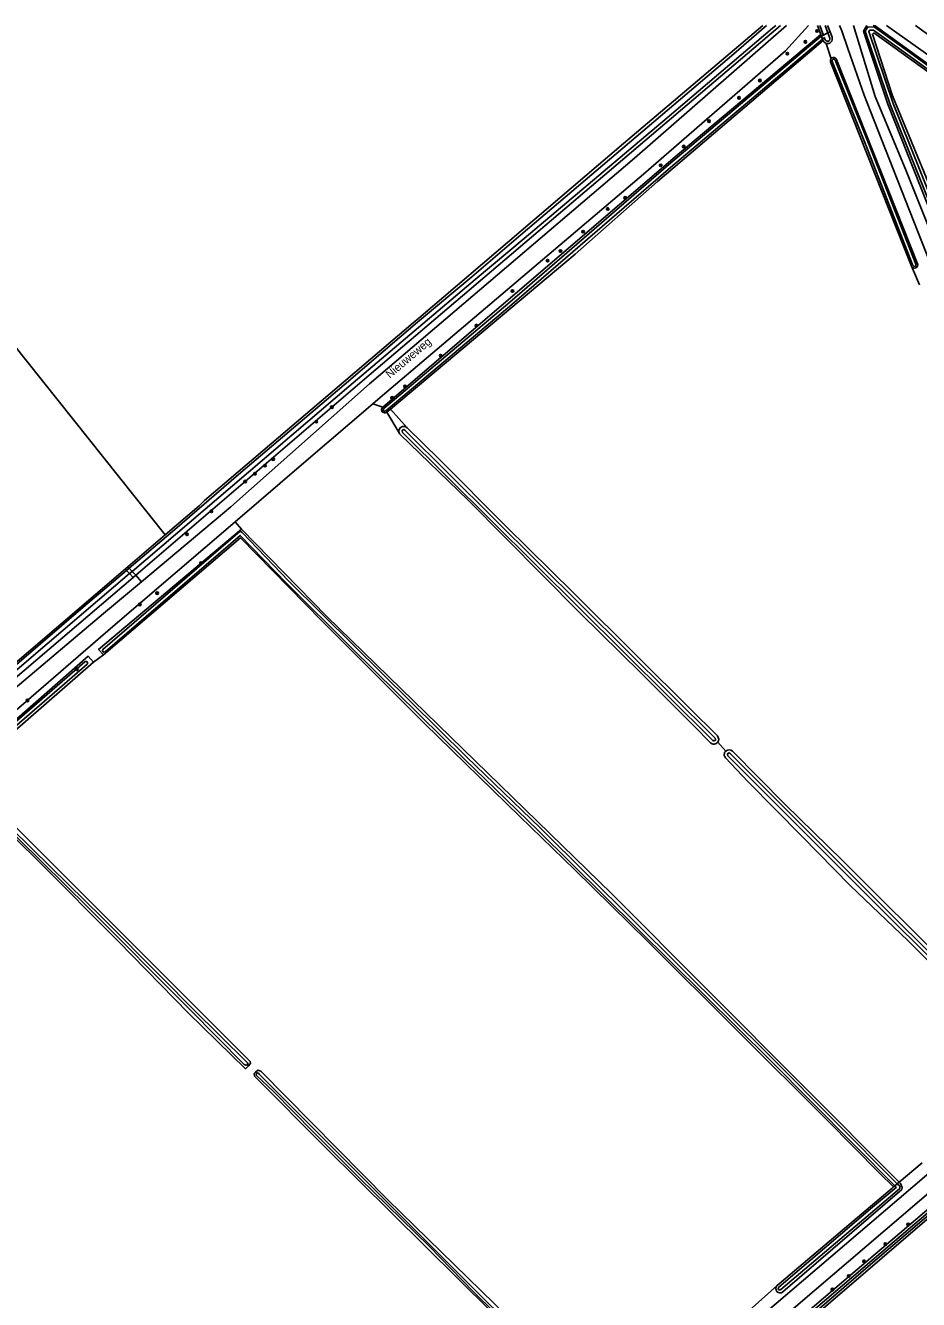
# Model space of a CAD drawing. Extents: x 141000 to 143000, y 400580 to 403500.
# Drawn here: x 142326.5 to 142605.5, y 403101.9 to 403500 of the extents above; entities that cross this region are included whole.
import ezdxf

# ---------------------------------------------------------------- set-up
doc = ezdxf.new("R2010")
doc.units = 0
for name, color, linetype in [('gg-anno-openbare ruimte label', 7, 'Continuous'), ('gg-knt-bronhoudergrens', 7, 'Continuous'), ('gg-knt-onverhard', 7, 'Continuous'), ('gg-knt-verharding', 7, 'Continuous'), ('gg-kntw-bovenkant insteek waterloop', 7, 'Continuous'), ('gg-kntw-waterlijn', 7, 'Continuous'), ('gg-kwrk-kunstwerk niveau 01', 7, 'Continuous'), ('gt-grn-groengrens', 7, 'Continuous'), ('gt-grn-vlakafsluiter', 7, 'Continuous'), ('gt-symb-boom', 7, 'Continuous')]:
    doc.layers.add(name, color=color, linetype=linetype)

# ---------------------------------------------------------------- blocks, each defined once
blk = doc.blocks.new('gt0-BOOM')
at = {"layer": 'gt-symb-boom'}
for radius in [0.4, 0.2]:
    blk.add_circle((0, 0), radius, dxfattribs=at)

msp = doc.modelspace()

# ---------------------------------------------------------------- linework, layer by layer
at = {"layer": 'gg-knt-bronhoudergrens'}
for p, q in [((142578.16, 403489.54), (142576.6, 403494.39)), ((142434.98, 403381.73), (142438.11, 403380.73)), ((142392, 403344.92), (142393.95, 403342.64)), ((142347.75, 403301), (142350.85, 403303.33)), ((142606.6, 403144.58), (142599.46, 403138.52)), ((142561.35, 403106.23), (142552.56, 403098.43))]:
    msp.add_line(p, q, dxfattribs=at)
at = {"layer": 'gg-knt-onverhard'}
for p, q in [((142370.19, 403340.85), (142264.78, 403472.87)), ((142603.33, 403424.78), (142605.82, 403418.96)), ((142439.4, 403379.2), (142443.25, 403372.7)), ((142440.52, 403380.15), (142445.72, 403374.27)), ((142545.29, 403273.28), (142542.79, 403276.02))]:
    msp.add_line(p, q, dxfattribs=at)
msp.add_lwpolyline([(142392, 403344.92), (142413.49, 403363.32), (142434.98, 403381.73)], dxfattribs=at)
at = {"layer": 'gg-knt-verharding'}
for points in [[(142362.71, 403326.12), (142390.63, 403349.55), (142434.03, 403388), (142516.8, 403458.52), (142564.26, 403500)], [(142434.98, 403381.73), (142437.3, 403383.72), (142519.54, 403453.56), (142563.96, 403492.12), (142571.1, 403500)], [(142580.86, 403500), (142581.54, 403498.3), (142583.38, 403492.84), (142588.51, 403478.21), (142592.66, 403467.56), (142616.56, 403406.94), (142630.76, 403372.28), (142649.91, 403327.04), (142662.96, 403294.46), (142683.41, 403242.72), (142693.01, 403213.78)], [(142585.17, 403500), (142591.93, 403477.83), (142601.39, 403455.15), (142647.31, 403340.12), (142678.4, 403262.94), (142686.61, 403242.88), (142692.87, 403227.3), (142697.08, 403214.59)], [(142595.45, 403500), (142629.17, 403476.1), (142673.83, 403443.54), (142712.26, 403416.36), (142765.07, 403379.18), (142812.16, 403344.83), (142845.71, 403319.06)], [(142604.52, 403500), (142632.22, 403479.92), (142678.54, 403445.48), (142714.62, 403419.55), (142767.02, 403382.42), (142814.6, 403347.5), (142848.6, 403321.46)], [(142129.43, 403121.45), (142155.13, 403142.95), (142217.83, 403196.26), (142255.83, 403229.33), (142298.44, 403265.98), (142313.46, 403277.45), (142353.81, 403312.2), (142392, 403344.92)], [(142362.71, 403326.12), (142350.92, 403316.23), (142295.63, 403269.59), (142253.14, 403232.93), (142215.27, 403199.68), (142179.13, 403169.58), (142151.11, 403147.23), (142116.02, 403117.12)], [(142479.87, 403025.12), (142638.66, 403160.83), (142676.84, 403193.65), (142683.65, 403199.18)], [(142674.81, 403197.87), (142603.73, 403137.12), (142467.85, 403021.07), (142458.4, 403012.83)]]:
    msp.add_lwpolyline(points, dxfattribs=at)
at = {"layer": 'gg-kntw-bovenkant insteek waterloop'}
for p, q in [((142573.89, 403500), (142574.94, 403497.22)), ((142577.1, 403500), (142577.86, 403497.99)), ((142577.86, 403497.99), (142578.48, 403496.34)), ((142579.91, 403489.34), (142605.17, 403425.56)), ((142578.05, 403488.6), (142603.33, 403424.78)), ((142440.52, 403380.15), (142439.4, 403379.2)), ((142358.48, 403330.82), (142370.19, 403340.85)), ((142308.84, 403267.11), (142347.75, 403301))]:
    msp.add_line(p, q, dxfattribs=at)
for points in [[(142360.96, 403328.21), (142433.9, 403390.74), (142562.39, 403500)], [(142370.19, 403340.85), (142380.73, 403349.88), (142382.43, 403351.52), (142447.61, 403407.09), (142449.39, 403408.56), (142513.33, 403463.13), (142556.85, 403500)], [(142574.94, 403497.22), (142573.01, 403495.54), (142530.23, 403459.57), (142438.11, 403380.73)], [(142589.32, 403500), (142588.32, 403498.23), (142595.87, 403475.4), (142640.71, 403362.28), (142654.81, 403325.96), (142665.77, 403298.81)], [(142706.45, 403413.83), (142670.95, 403440.11), (142621.19, 403476.34), (142591.57, 403497.67), (142591.07, 403497.32), (142597.37, 403478.02), (142617.11, 403430.15), (142651.96, 403339.43), (142667.73, 403300.2)], [(142591.29, 403500), (142591.97, 403499.88), (142622.44, 403477.83), (142672.13, 403441.68), (142707.63, 403415.45)], [(142440.52, 403380.15), (142498.24, 403428.49), (142523.95, 403451.27), (142575.67, 403495.29)], [(142445.72, 403374.27), (142455.72, 403364.51), (142476.68, 403343.4), (142497.61, 403322.83), (142518.26, 403302.28), (142533.82, 403286.76), (142542.65, 403277.99)], [(142540.53, 403275.86), (142535.49, 403280.89), (142518.85, 403297.65), (142499.67, 403316.48), (142464.83, 403351.63), (142443.54, 403372.2)], [(142350.85, 403303.33), (142349.35, 403305.04), (142393.95, 403342.64)], [(142393.95, 403342.64), (142420.59, 403315.46), (142509.69, 403228.66), (142599.46, 403138.52)], [(142350.85, 403303.33), (142393.65, 403339.89), (142418.94, 403314.04), (142451.22, 403281.81), (142480.92, 403252.78), (142498.12, 403236.12), (142520.84, 403213.86), (142577.06, 403157.85), (142593.32, 403141.35), (142597.66, 403137.08)], [(142299.37, 403280.46), (142327.45, 403304.24), (142358.48, 403330.82)], [(142360.17, 403327.53), (142350.24, 403319.02), (142301.84, 403277.83)], [(142347.75, 403301), (142346.08, 403302.9), (142307.25, 403268.89)], [(142640.83, 403175.69), (142632.08, 403184.36), (142617.37, 403198.78), (142602.25, 403214), (142584.13, 403231.28), (142569.16, 403246.61), (142552.14, 403263.78), (142545.24, 403271.12)], [(142547.36, 403273.24), (142563.78, 403256.69), (142581.71, 403239.05), (142615.56, 403205.33), (142633.58, 403187.1), (142640.07, 403180.8), (142642.94, 403177.82)], [(142309.46, 403259.61), (142330.82, 403238.62), (142355.47, 403213.84), (142377.46, 403191.34), (142395.21, 403174.01), (142396.05, 403174.82), (142396.76, 403175.68), (142396.66, 403176.3), (142311.35, 403261.52)], [(142481.78, 403021.02), (142481.71, 403021.74), (142482.3, 403022.59), (142554.77, 403084.41), (142620.69, 403140.5), (142669.87, 403182.48), (142687.06, 403197.98)], [(142483.71, 403020.26), (142525.74, 403056.39), (142561.18, 403086.54), (142610.32, 403128.81), (142624.25, 403139.94), (142649.26, 403161.21), (142688.71, 403196.01)], [(142505.71, 403065.34), (142506.6, 403066.31), (142506.51, 403066.7), (142477.15, 403096.43), (142439.74, 403133.06), (142400.05, 403173.27), (142399.06, 403173.53), (142398.34, 403172.97), (142397.99, 403172.55), (142398.03, 403171.68), (142420.22, 403149.41), (142472.11, 403098.02), (142504.57, 403065.62), (142505.29, 403065.33), (142505.71, 403065.34)], [(142599.46, 403138.52), (142599.83, 403138.16), (142600.39, 403136.91), (142600.24, 403136.27), (142563.12, 403104.25)], [(142561.35, 403106.23), (142597.31, 403136.68), (142597.66, 403137.08)]]:
    msp.add_lwpolyline(points, dxfattribs=at)
for centre, radius, start, end in [((142577.08, 403495.82), 1.5, 200.6888, 251.3899), ((142577.07, 403495.82), 1.5, 251.4555, 20.6376), ((142578.98, 403488.97), 1, 145.2392, 201.7865), ((142578.98, 403488.97), 1, 21.732, 145.2284), ((142604.24, 403425.2), 1, 205.2991, 21.083), ((142438.75, 403379.96), 1, 130.1251, 310.139), ((142444.66, 403373.2), 1.5, 45.2285, 199.6418), ((142444.66, 403373.2), 1.5, 199.5971, 221.6787), ((142541.59, 403276.92), 1.5, 322.7774, 45.2286), ((142541.59, 403276.93), 1.5, 225.2263, 322.7497), ((142546.3, 403272.18), 1.5, 132.4879, 224.8685), ((142546.3, 403272.17), 1.5, 44.954, 132.3944), ((142562.26, 403105.27), 1.33, 133.3054, 310.3417)]:
    msp.add_arc(centre, radius, start, end, dxfattribs=at)
at = {"layer": 'gg-kntw-waterlijn'}
for p, q in [((142576.3, 403500), (142577.18, 403497.66)), ((142577.18, 403497.66), (142577.77, 403496.08)), ((142541.94, 403277.28), (142445.01, 403373.56)), ((142541.24, 403276.57), (142444.31, 403372.85)), ((142358.9, 403330.38), (142358.11, 403329.71)), ((142359.05, 403328.72), (142359.83, 403329.4)), ((142345.1, 403301.17), (142307.51, 403268.59)), ((142308.18, 403267.85), (142345.76, 403300.42))]:
    msp.add_line(p, q, dxfattribs=at)
for points in [[(142358.9, 403330.38), (142373.18, 403342.47), (142393.08, 403359.64), (142426.12, 403387.66), (142448.99, 403407.32), (142465.94, 403421.44), (142481.31, 403434.55), (142526.99, 403473.4), (142547.75, 403491.1), (142557.98, 403500)], [(142359.83, 403329.4), (142427.51, 403387.19), (142466.98, 403420.61), (142482.35, 403433.44), (142526.94, 403471.15), (142559.9, 403499.15), (142560.93, 403500)], [(142574.7, 403500), (142575.55, 403497.74), (142575.74, 403497.22), (142575.13, 403496.71)], [(142666.15, 403299.08), (142651.19, 403336.44), (142635.5, 403378.1), (142612.5, 403435.81), (142596.66, 403475.31), (142588.83, 403498.25), (142589.71, 403499.59), (142591.74, 403499.5), (142602.77, 403491.6), (142624.99, 403475.45), (142665.07, 403446.19), (142707.33, 403415.05)], [(142666.99, 403299.68), (142652.12, 403336.8), (142636.43, 403378.46), (142613.43, 403436.18), (142597.59, 403475.66), (142589.93, 403498.11), (142590.23, 403498.56), (142591.4, 403498.51), (142602.18, 403490.79), (142624.4, 403474.64), (142664.48, 403445.38), (142706.74, 403414.25)], [(142575.13, 403496.71), (142527.35, 403456.42), (142477.8, 403413.53), (142438.43, 403380.34)], [(142575.51, 403495.71), (142528, 403455.66), (142478.45, 403412.77), (142439.08, 403379.58)], [(142575.51, 403495.71), (142576.12, 403496.23), (142576.28, 403495.8), (142576.37, 403495.55)], [(142578.51, 403488.78), (142588.98, 403462.89), (142603.77, 403425.02)], [(142604.7, 403425.38), (142589.91, 403463.25), (142579.44, 403489.16)], [(142598.83, 403138.04), (142559.92, 403177.23), (142487.39, 403249.14), (142464.32, 403271.44), (142429.07, 403306.24), (142408.81, 403326.4), (142394.16, 403341.53), (142393.62, 403341.95), (142350.71, 403305.05)], [(142598.05, 403137.4), (142559.21, 403176.52), (142486.69, 403248.43), (142463.62, 403270.72), (142428.36, 403305.53), (142408.1, 403325.7), (142393.63, 403340.64), (142351.36, 403304.29)], [(142299.84, 403279.96), (142306.99, 403285.97), (142324.59, 403301.04), (142345.22, 403318.81), (142358.11, 403329.71)], [(142300.74, 403279), (142333.32, 403306.76), (142359.05, 403328.72)], [(142641.53, 403176.4), (142589.01, 403228.64), (142545.95, 403271.82)], [(142642.24, 403177.11), (142589.72, 403229.35), (142546.65, 403272.53)], [(142309.88, 403260.03), (142346.12, 403224.39), (142377.85, 403192.55), (142394.86, 403175.33), (142395.44, 403175.13), (142395.81, 403175.2), (142395.94, 403175.33), (142396, 403175.57), (142395.9, 403175.82), (142395.65, 403176.08), (142378.94, 403192.62), (142369.16, 403202.48), (142350.34, 403221.35), (142334.54, 403236.9), (142322.01, 403249.21), (142311.34, 403259.81), (142310.48, 403260.64)], [(142539.75, 403069.03), (142571.55, 403096.47), (142590.52, 403112.78), (142621.9, 403139.63), (142635.03, 403150.68), (142670.33, 403180.77), (142687.14, 403196.02), (142687.17, 403196.46), (142686.58, 403196.81), (142672.82, 403184.17), (142653.56, 403167.53), (142576.08, 403101.46), (142534.01, 403065.68), (142512.19, 403047.04), (142485.11, 403024.16), (142482.37, 403021.67), (142482.62, 403021.36), (142482.89, 403021.25), (142483.2, 403021.26), (142486.53, 403023.79), (142515.15, 403048.22), (142539.75, 403069.03)], [(142505.54, 403066.59), (142465.72, 403106.02), (142445.51, 403126.26), (142417.84, 403153.94), (142399.55, 403172.35), (142399.3, 403172.58), (142399.01, 403172.67), (142398.79, 403172.62), (142398.6, 403172.33), (142398.64, 403171.92), (142403.96, 403166.86), (142416.5, 403154.22), (142431, 403139.72), (142452.61, 403118.55), (142466.48, 403104.32), (142486.25, 403084.85), (142505.04, 403066.21), (142505.38, 403066.03), (142505.57, 403066.19), (142505.61, 403066.41), (142505.54, 403066.59)], [(142598.05, 403137.4), (142598.52, 403136.92), (142591.16, 403130.7), (142561.85, 403105.73)], [(142562.5, 403104.97), (142591.81, 403129.93), (142599.64, 403136.56), (142599.61, 403137.26), (142598.83, 403138.04)]]:
    msp.add_lwpolyline(points, dxfattribs=at)
for centre, radius, start, end in [((142577.07, 403495.81), 0.75, 200.6143, 20.7035), ((142578.98, 403488.97), 0.5, 21.7695, 201.7695), ((142604.24, 403425.2), 0.5, 201.1073, 21.0911), ((142438.75, 403379.96), 0.5, 130.1621, 310.1089), ((142444.66, 403373.2), 0.5, 45.2028, 225.2021), ((142351.04, 403304.67), 0.5, 130.6813, 310.6455), ((142345.43, 403300.79), 0.5, 310.9316, 130.955), ((142541.59, 403276.92), 0.5, 225.1623, 45.1619), ((142546.3, 403272.18), 0.5, 45.0399, 224.8792), ((142562.18, 403105.35), 0.5, 130.476, 310.5152)]:
    msp.add_arc(centre, radius, start, end, dxfattribs=at)
at = {"layer": 'gg-kwrk-kunstwerk niveau 01'}
for p, q in [((142358.11, 403329.71), (142359.05, 403328.72)), ((142358.9, 403330.38), (142358.48, 403330.82)), ((142358.9, 403330.38), (142359.83, 403329.4)), ((142359.05, 403328.72), (142360.17, 403327.53)), ((142359.83, 403329.4), (142360.96, 403328.21)), ((142360.96, 403328.21), (142360.17, 403327.53))]:
    msp.add_line(p, q, dxfattribs=at)
msp.add_lwpolyline([(142358.11, 403329.71), (142357.7, 403330.15), (142358.48, 403330.82)], dxfattribs=at)
at = {"layer": 'gt-grn-groengrens'}
msp.add_line((142362.71, 403326.12), (142360.96, 403328.21), dxfattribs=at)
at = {"layer": 'gt-grn-vlakafsluiter'}
for p, q in [((142575.13, 403496.71), (142574.94, 403497.22)), ((142575.15, 403496.66), (142577.18, 403497.66)), ((142577.18, 403497.66), (142577.86, 403497.99)), ((142575.13, 403496.71), (142575.15, 403496.66)), ((142575.15, 403496.66), (142575.51, 403495.71)), ((142575.51, 403495.71), (142575.67, 403495.29)), ((142598.83, 403138.04), (142599.46, 403138.52)), ((142598.05, 403137.4), (142597.66, 403137.08)), ((142598.05, 403137.4), (142598.83, 403138.04))]:
    msp.add_line(p, q, dxfattribs=at)

# ---------------------------------------------------------------- block references
at = {"layer": 'gt-symb-boom'}
for p in [(142573.79, 403498.28), (142570.15, 403494.9), (142564.52, 403491.2), (142555.95, 403482.81), (142549.42, 403477.41), (142540.05, 403470.11), (142532.16, 403462.15), (142524.96, 403456.29), (142513.88, 403446.12), (142508.41, 403442.68), (142500.75, 403435.58), (142493.66, 403429.52), (142489.62, 403426.52), (142478.65, 403417.03), (142467.35, 403406.22), (142456.2, 403396.8), (142445.07, 403387.21), (142441.05, 403383.63), (142422.22, 403380.75), (142417.39, 403376.21), (142401.33, 403362.46), (142403.88, 403364.49), (142395.16, 403357.47), (142398.2, 403359.92), (142384.6, 403348.2), (142376.97, 403341.01), (142381.38, 403332.02), (142367.64, 403322.61), (142362.2, 403319.05), (142342.54, 403298.8), (142327.11, 403289.08), (142602.26, 403125.35), (142595.12, 403119.19), (142588.45, 403113.84), (142583.69, 403109.23), (142578.59, 403105)]:
    msp.add_blockref('gt0-BOOM', p, dxfattribs=at)

# ---------------------------------------------------------------- texts
at = {"layer": 'gg-anno-openbare ruimte label'}
msp.add_text('Nieuweweg', height=2.5, rotation=40.3, dxfattribs=at).set_placement((142440.34, 403389.62))

doc.saveas('drawing.dxf')
